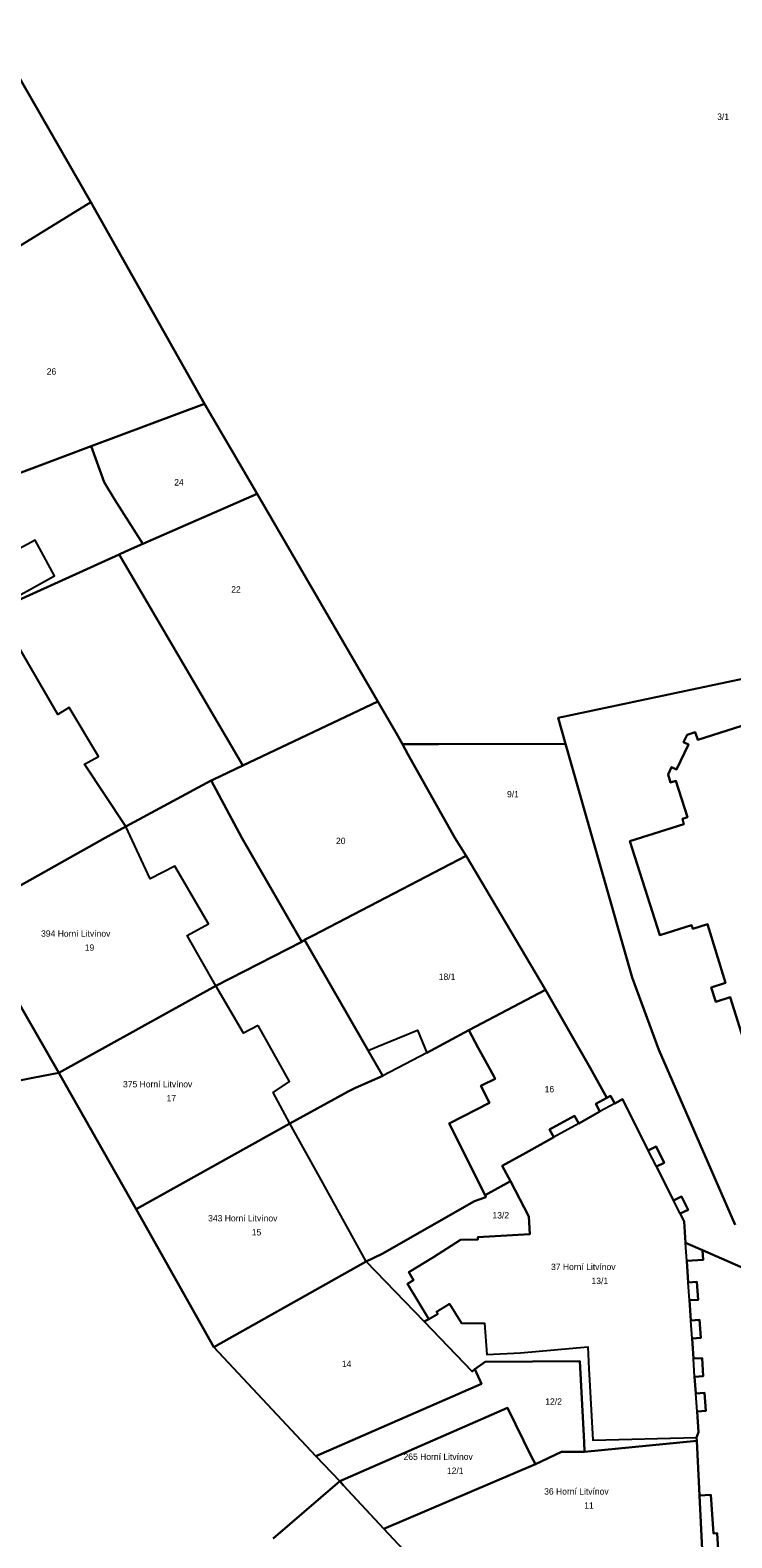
# Model space of a CAD drawing. Extents: x -792094 to -791524, y -979074 to -977761.
# Drawn here: x -791697.5 to -791642.5, y -978554.8 to -978436.7 of the extents above; entities that cross this region are included whole.
import ezdxf

# ---------------------------------------------------------------- set-up
doc = ezdxf.new("R2010")
doc.units = 0
doc.layers.add('katastr', color=7, linetype='Continuous')

msp = doc.modelspace()

# ---------------------------------------------------------------- linework, layer by layer
at = {"layer": 'katastr'}
for points in [[(-791639.24, -978372.34), (-791665.73, -978384.71), (-791679.28, -978391.82), (-791713.44, -978413.95), (-791712.96, -978414.79), (-791712, -978414.2), (-791699.5, -978436.46), (-791700.32, -978436.96), (-791699.69, -978438.07), (-791692.7, -978450.2), (-791683.8, -978465.99), (-791679.66, -978473.05), (-791670.22, -978489.33), (-791668.76, -978491.84), (-791668.28, -978492.67), (-791665.46, -978492.66), (-791655.51, -978492.64), (-791656.09, -978490.59), (-791634.23, -978485.99)], [(-791634.23, -978485.99), (-791656.09, -978490.59), (-791655.51, -978492.64), (-791650.28, -978510.95), (-791648.19, -978516.61), (-791642.22, -978530.31)], [(-791638.89, -978490.35), (-791645.14, -978492.33), (-791645.34, -978491.71), (-791645.98, -978491.92), (-791646.25, -978492.5), (-791645.86, -978492.68), (-791646.8, -978494.66), (-791647.2, -978494.47), (-791647.47, -978495.04), (-791647.27, -978495.66), (-791646.86, -978495.53), (-791645.94, -978498.38), (-791646.35, -978498.51), (-791646.24, -978498.93), (-791650.46, -978500.25), (-791648.11, -978507.63), (-791645.64, -978506.84), (-791645.54, -978507.13), (-791644.39, -978506.77), (-791642.96, -978511.36), (-791644.1, -978511.72), (-791643.74, -978512.84), (-791642.6, -978512.48), (-791641.14, -978517.12)], [(-791638.89, -978490.35), (-791645.14, -978492.33), (-791645.34, -978491.71), (-791645.98, -978491.92), (-791646.25, -978492.5), (-791645.86, -978492.68), (-791646.8, -978494.66), (-791647.2, -978494.47), (-791647.47, -978495.04), (-791647.27, -978495.66), (-791646.86, -978495.53), (-791645.94, -978498.38), (-791646.35, -978498.51), (-791646.24, -978498.93), (-791650.46, -978500.25), (-791648.11, -978507.63), (-791645.64, -978506.84), (-791645.54, -978507.13), (-791644.39, -978506.77), (-791642.96, -978511.36), (-791644.1, -978511.72), (-791643.74, -978512.84), (-791642.6, -978512.48), (-791641.14, -978517.12)], [(-791641.14, -978517.12), (-791642.6, -978512.48), (-791643.74, -978512.84), (-791644.1, -978511.72), (-791642.96, -978511.36), (-791644.39, -978506.77), (-791645.54, -978507.13), (-791645.64, -978506.84), (-791648.11, -978507.63), (-791650.46, -978500.25), (-791646.24, -978498.93), (-791646.35, -978498.51), (-791645.94, -978498.38), (-791646.86, -978495.53), (-791647.27, -978495.66), (-791647.47, -978495.04), (-791647.2, -978494.47), (-791646.8, -978494.66), (-791645.86, -978492.68), (-791646.25, -978492.5), (-791645.98, -978491.92), (-791645.34, -978491.71), (-791645.14, -978492.33), (-791638.89, -978490.35)], [(-791642.22, -978530.31), (-791648.19, -978516.61), (-791650.28, -978510.95), (-791655.51, -978492.64), (-791665.46, -978492.66), (-791668.28, -978492.67), (-791667.85, -978493.45), (-791664.17, -978500), (-791663.29, -978501.42), (-791657.07, -978511.91), (-791653.57, -978518.03), (-791652.27, -978520.37), (-791651.97, -978520.2), (-791651.64, -978520.8), (-791651.05, -978520.47), (-791649.02, -978524.49), (-791648.41, -978524.19), (-791647.77, -978525.46), (-791648.38, -978525.76), (-791647.05, -978528.41), (-791646.43, -978528.09), (-791645.9, -978529.13), (-791646.53, -978529.44), (-791646.22, -978530.06), (-791646.1, -978531.73), (-791644.78, -978532.31), (-791635.85, -978536.21)], [(-791704.72, -978520.29), (-791697.24, -978518.8), (-791695.21, -978518.4), (-791702.33, -978506.02)], [(-791678.41, -978554.9), (-791674.68, -978551.67), (-791673.2, -978550.39), (-791675.08, -978548.44), (-791683.07, -978539.9), (-791689.15, -978529.1), (-791695.21, -978518.4), (-791697.24, -978518.8), (-791704.72, -978520.29)], [(-791635.85, -978536.21), (-791644.78, -978532.31), (-791644.73, -978533.05), (-791646.01, -978533.14), (-791645.89, -978534.83), (-791645.21, -978534.78), (-791645.12, -978536.19), (-791645.8, -978536.23), (-791645.69, -978537.82), (-791645.01, -978537.77), (-791644.91, -978539.18), (-791645.59, -978539.23), (-791645.48, -978540.8), (-791644.81, -978540.76), (-791644.71, -978542.17), (-791645.39, -978542.22), (-791645.3, -978543.53), (-791644.62, -978543.48), (-791644.52, -978544.89), (-791645.2, -978544.93), (-791645.09, -978546.56), (-791645.24, -978546.98), (-791645.22, -978547.25), (-791645.01, -978551.51), (-791644.11, -978551.47), (-791643.91, -978554.49), (-791643.61, -978554.47), (-791643.54, -978555.76)], [(-791665.2, -978559), (-791669.74, -978554.12), (-791672.91, -978550.73), (-791673.2, -978550.39), (-791674.68, -978551.67), (-791678.41, -978554.9)]]:
    msp.add_lwpolyline(points, dxfattribs=at)
for points in [[(-791704.84, -978457.66), (-791692.7, -978450.2), (-791699.69, -978438.07), (-791705.15, -978441.38), (-791706.69, -978442.32), (-791711.35, -978445.15)], [(-791692.67, -978469.32), (-791683.8, -978465.99), (-791692.7, -978450.2), (-791704.84, -978457.66), (-791709.08, -978460.25), (-791702.58, -978473.05), (-791702.04, -978472.85), (-791701.59, -978472.66)], [(-791683.8, -978465.99), (-791692.67, -978469.32), (-791691.65, -978472.15), (-791690.81, -978473.51), (-791688.64, -978476.97), (-791679.66, -978473.05)], [(-791704.08, -978473.28), (-791705.72, -978473.89), (-791707.45, -978474.56), (-791717.87, -978478.58), (-791712.17, -978488.46), (-791700.06, -978482.13), (-791690.47, -978477.8), (-791689.99, -978477.58), (-791688.64, -978476.97), (-791690.81, -978473.51), (-791691.65, -978472.15), (-791692.67, -978469.32), (-791701.59, -978472.66), (-791702.04, -978472.85), (-791702.58, -978473.05)], [(-791717.87, -978478.58), (-791712.17, -978488.46), (-791700.06, -978482.13), (-791700.1, -978481.97), (-791695.54, -978479.47), (-791697.06, -978476.68), (-791701.18, -978478.9), (-791702.01, -978477.39), (-791700.43, -978476.66), (-791700.22, -978477.12), (-791699.93, -978477.04), (-791701.59, -978472.66), (-791702.04, -978472.85), (-791702.58, -978473.05), (-791704.08, -978473.28), (-791705.72, -978473.89), (-791707.45, -978474.56)], [(-791690.47, -978477.8), (-791680.78, -978494.33), (-791670.22, -978489.33), (-791679.66, -978473.05), (-791688.64, -978476.97), (-791689.99, -978477.58)], [(-791705.66, -978500), (-791702.33, -978506.02), (-791691.58, -978500), (-791689.96, -978499.12), (-791683.28, -978495.52), (-791683.09, -978495.42), (-791680.78, -978494.33), (-791690.47, -978477.8), (-791700.06, -978482.13), (-791712.17, -978488.46)], [(-791712.17, -978488.46), (-791705.66, -978500), (-791702.33, -978506.02), (-791691.58, -978500), (-791689.96, -978499.12), (-791693.19, -978494.23), (-791692.11, -978493.64), (-791694.41, -978489.79), (-791695.3, -978490.34), (-791700.06, -978482.13)], [(-791675.27, -978507.64), (-791663.29, -978501.42), (-791664.17, -978500), (-791667.85, -978493.45), (-791668.28, -978492.67), (-791668.76, -978491.84), (-791670.22, -978489.33), (-791680.78, -978494.33), (-791683.09, -978495.42), (-791683.28, -978495.52), (-791680.86, -978500), (-791676.17, -978508.15), (-791675.96, -978508)], [(-791695.21, -978518.4), (-791682.9, -978511.6), (-791676.17, -978508.15), (-791680.86, -978500), (-791683.28, -978495.52), (-791689.96, -978499.12), (-791691.58, -978500), (-791702.33, -978506.02)], [(-791702.33, -978506.02), (-791695.21, -978518.4), (-791682.9, -978511.6), (-791685.15, -978507.64), (-791683.48, -978506.74), (-791686.11, -978502.21), (-791688.06, -978503.2), (-791689.96, -978499.12), (-791691.58, -978500)], [(-791666.38, -978516.83), (-791663.07, -978515.08), (-791657.07, -978511.91), (-791663.29, -978501.42), (-791675.27, -978507.64), (-791675.96, -978508), (-791670.96, -978516.65), (-791670.3, -978516.38), (-791667.1, -978515.06)], [(-791695.21, -978518.4), (-791689.15, -978529.1), (-791677.1, -978522.37), (-791672.54, -978519.88), (-791671.97, -978519.58), (-791669.81, -978518.64), (-791670.96, -978516.65), (-791675.96, -978508), (-791676.17, -978508.15), (-791682.9, -978511.6)], [(-791679.58, -978514.71), (-791680.74, -978515.3), (-791682.9, -978511.6), (-791695.21, -978518.4), (-791689.15, -978529.1), (-791677.1, -978522.37), (-791678.41, -978519.95), (-791677.13, -978519.1)], [(-791661.45, -978520.77), (-791664.63, -978522.39), (-791661.8, -978527.98), (-791659.83, -978526.9), (-791660.46, -978525.7), (-791658.85, -978524.81), (-791658.15, -978524.42), (-791656.42, -978523.46), (-791656.75, -978522.86), (-791654.79, -978521.77), (-791654.46, -978522.37), (-791652.81, -978521.45), (-791653.14, -978520.85), (-791652.27, -978520.37), (-791653.57, -978518.03), (-791657.07, -978511.91), (-791663.07, -978515.08), (-791662.34, -978516.44), (-791661.96, -978517.15), (-791661.13, -978518.68), (-791661.03, -978518.87), (-791661.98, -978519.36), (-791662.14, -978519.44)], [(-791683.07, -978539.9), (-791682.29, -978539.46), (-791671.14, -978533.18), (-791669.88, -978532.59), (-791662.64, -978528.46), (-791661.74, -978528.15), (-791661.8, -978527.98), (-791664.63, -978522.39), (-791661.45, -978520.77), (-791662.14, -978519.44), (-791661.98, -978519.36), (-791661.03, -978518.87), (-791661.13, -978518.68), (-791661.96, -978517.15), (-791662.34, -978516.44), (-791663.07, -978515.08), (-791666.38, -978516.83), (-791669.81, -978518.64), (-791671.97, -978519.58), (-791672.54, -978519.88), (-791677.1, -978522.37), (-791689.15, -978529.1)], [(-791645.2, -978544.93), (-791644.52, -978544.89), (-791644.62, -978543.48), (-791645.3, -978543.53), (-791645.39, -978542.22), (-791644.71, -978542.17), (-791644.81, -978540.76), (-791645.48, -978540.8), (-791645.59, -978539.23), (-791644.91, -978539.18), (-791645.01, -978537.77), (-791645.69, -978537.82), (-791645.8, -978536.23), (-791645.12, -978536.19), (-791645.21, -978534.78), (-791645.89, -978534.83), (-791646.01, -978533.14), (-791644.73, -978533.05), (-791644.78, -978532.31), (-791646.1, -978531.73), (-791646.22, -978530.06), (-791646.53, -978529.44), (-791645.9, -978529.13), (-791646.43, -978528.09), (-791647.05, -978528.41), (-791648.38, -978525.76), (-791647.77, -978525.46), (-791648.41, -978524.19), (-791649.02, -978524.49), (-791651.05, -978520.47), (-791651.64, -978520.8), (-791651.97, -978520.2), (-791652.27, -978520.37), (-791653.14, -978520.85), (-791652.81, -978521.45), (-791654.46, -978522.37), (-791654.79, -978521.77), (-791656.75, -978522.86), (-791656.42, -978523.46), (-791658.15, -978524.42), (-791658.85, -978524.81), (-791660.46, -978525.7), (-791659.83, -978526.9), (-791658.38, -978529.66), (-791658.3, -978531.04), (-791662.39, -978531.28), (-791662.38, -978531.46), (-791663.73, -978531.5), (-791665.86, -978532.86), (-791667.79, -978534.03), (-791667.43, -978534.65), (-791667.9, -978534.93), (-791666.23, -978537.7), (-791666.57, -978537.9), (-791662.83, -978541.8), (-791662.6, -978541.63), (-791661.81, -978541.05), (-791654.38, -978540.99), (-791654.05, -978547.34), (-791654.01, -978548.1), (-791645.22, -978547.25), (-791645.24, -978546.98), (-791645.09, -978546.56)], [(-791667.79, -978534.03), (-791667.43, -978534.65), (-791667.9, -978534.93), (-791666.23, -978537.7), (-791665.52, -978537.28), (-791665.61, -978537.13), (-791664.61, -978536.51), (-791663.67, -978538.01), (-791661.86, -978538.01), (-791661.67, -978540.47), (-791659.04, -978540.34), (-791653.77, -978539.88), (-791653.67, -978541.6), (-791653.6, -978542.94), (-791653.36, -978547.18), (-791645.24, -978546.98), (-791645.09, -978546.56), (-791645.2, -978544.93), (-791645.3, -978543.53), (-791645.39, -978542.22), (-791645.48, -978540.8), (-791645.59, -978539.23), (-791645.69, -978537.82), (-791645.8, -978536.23), (-791645.89, -978534.83), (-791646.01, -978533.14), (-791646.1, -978531.73), (-791646.22, -978530.06), (-791646.53, -978529.44), (-791647.05, -978528.41), (-791648.38, -978525.76), (-791649.02, -978524.49), (-791651.05, -978520.47), (-791651.64, -978520.8), (-791652.81, -978521.45), (-791654.46, -978522.37), (-791656.42, -978523.46), (-791658.15, -978524.42), (-791658.85, -978524.81), (-791660.46, -978525.7), (-791659.83, -978526.9), (-791658.38, -978529.66), (-791658.3, -978531.04), (-791662.39, -978531.28), (-791662.38, -978531.46), (-791663.73, -978531.5), (-791665.86, -978532.86)], [(-791682.29, -978539.46), (-791671.14, -978533.18), (-791674.66, -978526.8), (-791677.1, -978522.37), (-791689.15, -978529.1), (-791683.07, -978539.9)], [(-791662.64, -978528.46), (-791669.88, -978532.59), (-791671.14, -978533.18), (-791666.57, -978537.9), (-791666.23, -978537.7), (-791667.9, -978534.93), (-791667.43, -978534.65), (-791667.79, -978534.03), (-791665.86, -978532.86), (-791663.73, -978531.5), (-791662.38, -978531.46), (-791662.39, -978531.28), (-791658.3, -978531.04), (-791658.38, -978529.66), (-791659.83, -978526.9), (-791661.8, -978527.98), (-791661.74, -978528.15)], [(-791682.29, -978539.46), (-791683.07, -978539.9), (-791675.08, -978548.44), (-791662.1, -978542.76), (-791662.6, -978541.63), (-791662.83, -978541.8), (-791666.57, -978537.9), (-791671.14, -978533.18)], [(-791675.08, -978548.44), (-791673.2, -978550.39), (-791660.05, -978544.65), (-791658.16, -978548.48), (-791657.87, -978549.06), (-791655.81, -978548.1), (-791654.01, -978548.1), (-791654.05, -978547.34), (-791654.38, -978540.99), (-791661.81, -978541.05), (-791662.6, -978541.63), (-791662.1, -978542.76)], [(-791658.16, -978548.48), (-791660.05, -978544.65), (-791673.2, -978550.39), (-791672.91, -978550.73), (-791669.74, -978554.12), (-791657.87, -978549.06)], [(-791658.16, -978548.48), (-791660.05, -978544.65), (-791673.2, -978550.39), (-791672.91, -978550.73), (-791669.74, -978554.12), (-791657.87, -978549.06)], [(-791644.6, -978559.97), (-791645.01, -978551.51), (-791645.22, -978547.25), (-791654.01, -978548.1), (-791655.81, -978548.1), (-791657.87, -978549.06), (-791669.74, -978554.12), (-791665.2, -978559), (-791652.17, -978555.67), (-791646.17, -978562.44), (-791644.41, -978563.77), (-791644.5, -978561.99)], [(-791669.74, -978554.12), (-791665.2, -978559), (-791652.17, -978555.67), (-791646.17, -978562.44), (-791644.41, -978563.77), (-791644.5, -978561.99), (-791644.6, -978559.97), (-791645.01, -978551.51), (-791645.22, -978547.25), (-791654.01, -978548.1), (-791655.81, -978548.1), (-791657.87, -978549.06)], [(-791643, -978559.89), (-791643.06, -978558.77), (-791642.74, -978558.76), (-791642.84, -978557.24), (-791643.12, -978557.24), (-791643.24, -978555.76), (-791643.54, -978555.76), (-791643.61, -978554.47), (-791643.91, -978554.49), (-791644.11, -978551.47), (-791645.01, -978551.51), (-791644.6, -978559.97)]]:
    msp.add_lwpolyline(points, close=True, dxfattribs=at)

# ---------------------------------------------------------------- texts
for s, p in [('3/1', (-791643.62, -978443.76)), ('26', (-791696.16, -978463.72)), ('24', (-791686.17, -978472.4)), ('22', (-791681.7, -978480.79)), ('9/1', (-791660.09, -978496.83)), ('20', (-791673.49, -978500.49)), ('394 Horní Litvínov', (-791696.6, -978507.75)), ('19', (-791693.18, -978508.85)), ('18/1', (-791665.44, -978511.13)), ('375 Horní Litvínov', (-791690.18, -978519.55)), ('17', (-791686.77, -978520.65)), ('16', (-791657.14, -978519.94)), ('343 Horní Litvínov', (-791683.51, -978530.05)), ('13/2', (-791661.23, -978529.82)), ('15', (-791680.09, -978531.15)), ('37 Horní Litvínov', (-791656.64, -978533.86)), ('13/1', (-791653.47, -978534.96)), ('14', (-791673.03, -978541.46)), ('12/2', (-791657.09, -978544.41)), ('265 Horní Litvínov', (-791668.2, -978548.73)), ('12/1', (-791664.8, -978549.83)), ('36 Horní Litvínov', (-791657.18, -978551.45)), ('11', (-791654.04, -978552.55))]:
    msp.add_text(s, height=0.5, dxfattribs=at).set_placement(p)

doc.saveas('drawing.dxf')
